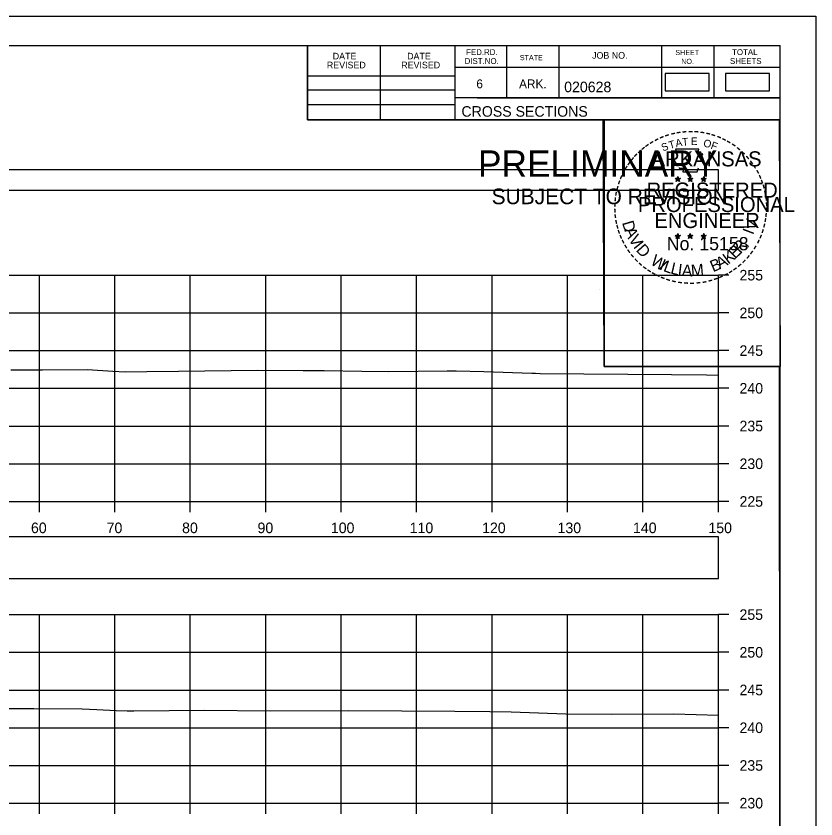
# Model space of a CAD drawing. Extents: x 1369627 to 1374022, y 380035 to 398173.
# Drawn here: x 1372155.4 to 1372261.5, y 382279 to 382385.5 of the extents above; entities that cross this region are included whole.
import ezdxf

# ---------------------------------------------------------------- set-up
doc = ezdxf.new("R2010")
doc.units = 0
for name, color, linetype in [('Default', 7, 'Continuous'), ('R_Axis', 7, 'Continuous'), ('R_Axis Annot', 7, 'Continuous'), ('R_Border', 7, 'Continuous'), ('R_Border PE', 7, 'Continuous'), ('R_Border Prem', 7, 'Continuous'), ('R_Exist Surface', 7, 'Continuous'), ('R_Grid', 7, 'Continuous'), ('R_No Plot', 7, 'Continuous')]:
    doc.layers.add(name, color=color, linetype=linetype)

msp = doc.modelspace()

# ---------------------------------------------------------------- linework, layer by layer
at = {"layer": 'Default'}
for points in [[(1372241.46, 382375.56), (1372247.3, 382375.56), (1372247.3, 382377.87), (1372241.46, 382377.87)], [(1372249.48, 382375.56), (1372255.32, 382375.56), (1372255.32, 382377.87), (1372249.48, 382377.87)], [(1371948.53, 382362.4), (1372248.53, 382362.4), (1372248.53, 382365.11), (1371948.53, 382365.11)], [(1371948.53, 382310.92), (1372248.53, 382310.92), (1372248.53, 382316.44), (1371948.53, 382316.44)]]:
    msp.add_lwpolyline(points, close=True, dxfattribs=at)
at = {"layer": 'R_Axis'}
for p, q in [((1372248.53, 382321.14), (1372248.53, 382351.14)), ((1372249.93, 382351.14), (1372248.53, 382351.14)), ((1372249.93, 382346.14), (1372248.53, 382346.14)), ((1372249.93, 382341.14), (1372248.53, 382341.14)), ((1372249.93, 382336.14), (1372248.53, 382336.14)), ((1372249.93, 382331.14), (1372248.53, 382331.14)), ((1372249.93, 382326.14), (1372248.53, 382326.14)), ((1371948.53, 382321.14), (1372248.53, 382321.14)), ((1372158.53, 382319.74), (1372158.53, 382321.14)), ((1372168.53, 382319.74), (1372168.53, 382321.14)), ((1372178.53, 382319.74), (1372178.53, 382321.14)), ((1372188.53, 382319.74), (1372188.53, 382321.14)), ((1372198.53, 382319.74), (1372198.53, 382321.14)), ((1372208.53, 382319.74), (1372208.53, 382321.14)), ((1372218.53, 382319.74), (1372218.53, 382321.14)), ((1372228.53, 382319.74), (1372228.53, 382321.14)), ((1372238.53, 382319.74), (1372238.53, 382321.14)), ((1372248.53, 382319.74), (1372248.53, 382321.14)), ((1372249.93, 382321.14), (1372248.53, 382321.14)), ((1372248.53, 382281.14), (1372248.53, 382306.14)), ((1372249.93, 382306.14), (1372248.53, 382306.14)), ((1372249.93, 382301.14), (1372248.53, 382301.14)), ((1372249.93, 382296.14), (1372248.53, 382296.14)), ((1372249.93, 382291.14), (1372248.53, 382291.14)), ((1372249.93, 382286.14), (1372248.53, 382286.14)), ((1371948.53, 382281.14), (1372248.53, 382281.14)), ((1372158.53, 382279.74), (1372158.53, 382281.14)), ((1372168.53, 382279.74), (1372168.53, 382281.14)), ((1372178.53, 382279.74), (1372178.53, 382281.14)), ((1372188.53, 382279.74), (1372188.53, 382281.14)), ((1372198.53, 382279.74), (1372198.53, 382281.14)), ((1372208.53, 382279.74), (1372208.53, 382281.14)), ((1372218.53, 382279.74), (1372218.53, 382281.14)), ((1372228.53, 382279.74), (1372228.53, 382281.14)), ((1372238.53, 382279.74), (1372238.53, 382281.14)), ((1372248.53, 382279.74), (1372248.53, 382281.14)), ((1372249.93, 382281.14), (1372248.53, 382281.14))]:
    msp.add_line(p, q, dxfattribs=at)
at = {"layer": 'R_Border'}
for p, q in [((1371940.53, 382381.6), (1372256.71, 382381.6)), ((1372194.07, 382371.72), (1372194.07, 382381.6)), ((1372203.75, 382371.72), (1372203.75, 382381.6)), ((1372213.61, 382381.6), (1372213.61, 382371.72)), ((1372220.45, 382381.6), (1372220.45, 382374.66)), ((1372227.39, 382381.6), (1372227.39, 382374.66)), ((1372240.97, 382381.6), (1372240.97, 382374.66)), ((1372247.91, 382381.6), (1372247.91, 382374.66)), ((1372256.71, 382176.14), (1372256.71, 382381.6)), ((1372256.71, 382378.66), (1372213.61, 382378.66)), ((1372256.71, 382378.68), (1372256.71, 382378.68)), ((1372194.07, 382377.58), (1372213.61, 382377.58)), ((1372194.07, 382375.72), (1372213.61, 382375.72)), ((1372256.71, 382374.66), (1372213.61, 382374.66)), ((1372216.57, 382374.66), (1372256.71, 382374.66)), ((1372194.07, 382373.78), (1372213.61, 382373.78)), ((1372256.71, 382371.72), (1372194.07, 382371.72))]:
    msp.add_line(p, q, dxfattribs=at)
at = {"layer": 'R_Border PE'}
for p, q in [((1372242.79, 382363.97), (1372243.14, 382363.86)), ((1372242.79, 382363.97), (1372243.05, 382363.93)), ((1372242.79, 382363.97), (1372243.03, 382363.85)), ((1372242.93, 382363.57), (1372243.14, 382363.86)), ((1372242.93, 382363.57), (1372243.05, 382363.81)), ((1372242.93, 382363.57), (1372243.14, 382363.78)), ((1372243.14, 382364.23), (1372243.1, 382363.98)), ((1372243.14, 382363.86), (1372243.14, 382364.23)), ((1372243.14, 382364.23), (1372243.19, 382363.98)), ((1372243.49, 382363.97), (1372243.14, 382363.86)), ((1372243.36, 382363.57), (1372243.14, 382363.86)), ((1372243.36, 382363.57), (1372243.14, 382363.78)), ((1372243.49, 382363.97), (1372243.2, 382363.93)), ((1372243.36, 382363.57), (1372243.22, 382363.86)), ((1372243.49, 382363.97), (1372243.29, 382363.87)), ((1372244.46, 382363.97), (1372244.81, 382363.86)), ((1372244.46, 382363.97), (1372244.72, 382363.93)), ((1372244.46, 382363.97), (1372244.7, 382363.85)), ((1372244.6, 382363.57), (1372244.81, 382363.86)), ((1372244.6, 382363.57), (1372244.72, 382363.81)), ((1372244.6, 382363.57), (1372244.81, 382363.78)), ((1372244.81, 382364.23), (1372244.77, 382363.98)), ((1372244.81, 382363.86), (1372244.81, 382364.23)), ((1372244.81, 382364.23), (1372244.86, 382363.98)), ((1372245.16, 382363.97), (1372244.81, 382363.86)), ((1372245.03, 382363.57), (1372244.81, 382363.86)), ((1372245.03, 382363.57), (1372244.81, 382363.78)), ((1372245.16, 382363.97), (1372244.87, 382363.93)), ((1372245.03, 382363.57), (1372244.89, 382363.86)), ((1372245.16, 382363.97), (1372244.96, 382363.87)), ((1372246.23, 382363.96), (1372246.58, 382363.85)), ((1372246.23, 382363.96), (1372246.48, 382363.92)), ((1372246.23, 382363.96), (1372246.47, 382363.84)), ((1372246.36, 382363.55), (1372246.58, 382363.85)), ((1372246.36, 382363.55), (1372246.49, 382363.8)), ((1372246.36, 382363.55), (1372246.58, 382363.77)), ((1372246.58, 382364.22), (1372246.54, 382363.96)), ((1372246.58, 382363.85), (1372246.58, 382364.22)), ((1372246.58, 382364.22), (1372246.63, 382363.97)), ((1372246.92, 382363.96), (1372246.58, 382363.85)), ((1372246.79, 382363.55), (1372246.58, 382363.85)), ((1372246.79, 382363.55), (1372246.58, 382363.77)), ((1372246.92, 382363.96), (1372246.64, 382363.91)), ((1372246.79, 382363.55), (1372246.65, 382363.85)), ((1372246.92, 382363.96), (1372246.72, 382363.86)), ((1372242.79, 382356.4), (1372243.14, 382356.29)), ((1372242.79, 382356.4), (1372243.04, 382356.36)), ((1372242.79, 382356.4), (1372243.03, 382356.28)), ((1372242.92, 382355.99), (1372243.14, 382356.29)), ((1372242.92, 382355.99), (1372243.05, 382356.24)), ((1372242.92, 382355.99), (1372243.14, 382356.21)), ((1372243.14, 382356.66), (1372243.1, 382356.4)), ((1372243.14, 382356.29), (1372243.14, 382356.66)), ((1372243.14, 382356.66), (1372243.19, 382356.41)), ((1372243.49, 382356.4), (1372243.14, 382356.29)), ((1372243.35, 382355.99), (1372243.14, 382356.29)), ((1372243.35, 382355.99), (1372243.14, 382356.21)), ((1372243.49, 382356.4), (1372243.2, 382356.35)), ((1372243.35, 382355.99), (1372243.22, 382356.28)), ((1372243.49, 382356.4), (1372243.28, 382356.3)), ((1372244.46, 382356.4), (1372244.81, 382356.29)), ((1372244.46, 382356.4), (1372244.71, 382356.36)), ((1372244.46, 382356.4), (1372244.7, 382356.28)), ((1372244.59, 382355.99), (1372244.81, 382356.29)), ((1372244.59, 382355.99), (1372244.72, 382356.24)), ((1372244.59, 382355.99), (1372244.81, 382356.21)), ((1372244.81, 382356.66), (1372244.77, 382356.4)), ((1372244.81, 382356.29), (1372244.81, 382356.66)), ((1372244.81, 382356.66), (1372244.86, 382356.41)), ((1372245.16, 382356.4), (1372244.81, 382356.29)), ((1372245.02, 382355.99), (1372244.81, 382356.29)), ((1372245.02, 382355.99), (1372244.81, 382356.21)), ((1372245.16, 382356.4), (1372244.87, 382356.35)), ((1372245.02, 382355.99), (1372244.88, 382356.28)), ((1372245.16, 382356.4), (1372244.95, 382356.3)), ((1372246.23, 382356.39), (1372246.58, 382356.28)), ((1372246.23, 382356.39), (1372246.48, 382356.35)), ((1372246.23, 382356.39), (1372246.46, 382356.27)), ((1372246.36, 382355.98), (1372246.58, 382356.28)), ((1372246.36, 382355.98), (1372246.49, 382356.23)), ((1372246.36, 382355.98), (1372246.57, 382356.2)), ((1372246.58, 382356.65), (1372246.53, 382356.39)), ((1372246.79, 382355.98), (1372246.57, 382356.2)), ((1372246.58, 382356.28), (1372246.58, 382356.65)), ((1372246.58, 382356.65), (1372246.62, 382356.4)), ((1372246.92, 382356.39), (1372246.58, 382356.28)), ((1372246.79, 382355.98), (1372246.58, 382356.28)), ((1372246.92, 382356.39), (1372246.64, 382356.34)), ((1372246.79, 382355.98), (1372246.65, 382356.27)), ((1372246.92, 382356.39), (1372246.72, 382356.29))]:
    msp.add_line(p, q, dxfattribs=at)
for points in [[(1372242.84, 382367.85), (1372243.1, 382367.03)], [(1372246.35, 382366.93), (1372246.49, 382367.21), (1372245.8, 382367.19), (1372245.95, 382367.85), (1372242.84, 382367.85)], [(1372243.33, 382365.43), (1372243.33, 382365.34), (1372243.89, 382365.32), (1372243.84, 382364.85), (1372245.71, 382364.85), (1372245.91, 382365.39)], [(1372243.14, 382364.23), (1372243.36, 382363.57), (1372242.79, 382363.97), (1372243.49, 382363.97), (1372242.93, 382363.57), (1372243.14, 382364.23)], [(1372244.81, 382364.23), (1372245.03, 382363.57), (1372244.46, 382363.97), (1372245.16, 382363.97), (1372244.6, 382363.57), (1372244.81, 382364.23)], [(1372246.58, 382364.22), (1372246.79, 382363.55), (1372246.23, 382363.96), (1372246.92, 382363.96), (1372246.36, 382363.55), (1372246.58, 382364.22)], [(1372243.14, 382356.66), (1372243.35, 382355.99), (1372242.79, 382356.4), (1372243.49, 382356.4), (1372242.92, 382355.99), (1372243.14, 382356.66)], [(1372244.81, 382356.66), (1372245.02, 382355.99), (1372244.46, 382356.4), (1372245.16, 382356.4), (1372244.59, 382355.99), (1372244.81, 382356.66)], [(1372246.58, 382356.65), (1372246.79, 382355.98), (1372246.23, 382356.39), (1372246.92, 382356.39), (1372246.36, 382355.98), (1372246.58, 382356.65)]]:
    msp.add_lwpolyline(points, dxfattribs=at)
for centre, radius in [((1372243.14, 382363.86), 0.172), ((1372243.14, 382363.86), 0.145), ((1372243.14, 382363.86), 0.116), ((1372243.14, 382363.86), 0.0991), ((1372243.14, 382363.86), 0.0747), ((1372243.14, 382363.86), 0.0495), ((1372243.14, 382363.86), 0.0296), ((1372244.81, 382363.86), 0.172), ((1372244.81, 382363.86), 0.145), ((1372244.81, 382363.86), 0.116), ((1372244.81, 382363.86), 0.0991), ((1372244.81, 382363.86), 0.0747), ((1372244.81, 382363.86), 0.0495), ((1372244.81, 382363.86), 0.0296), ((1372246.58, 382363.85), 0.172), ((1372246.58, 382363.85), 0.145), ((1372246.58, 382363.85), 0.116), ((1372246.58, 382363.85), 0.0991), ((1372246.58, 382363.85), 0.0747), ((1372246.58, 382363.85), 0.0495), ((1372246.58, 382363.85), 0.0296), ((1372243.14, 382356.29), 0.172), ((1372243.14, 382356.29), 0.145), ((1372243.14, 382356.29), 0.116), ((1372243.14, 382356.29), 0.0991), ((1372243.14, 382356.29), 0.0747), ((1372243.14, 382356.29), 0.0495), ((1372243.14, 382356.29), 0.0296), ((1372244.81, 382356.29), 0.172), ((1372244.81, 382356.29), 0.145), ((1372244.81, 382356.29), 0.116), ((1372244.81, 382356.29), 0.0991), ((1372244.81, 382356.29), 0.0747), ((1372244.81, 382356.29), 0.0495), ((1372244.81, 382356.29), 0.0296), ((1372246.57, 382356.28), 0.172), ((1372246.57, 382356.28), 0.145), ((1372246.57, 382356.28), 0.116), ((1372246.57, 382356.28), 0.0991), ((1372246.57, 382356.28), 0.0747), ((1372246.57, 382356.28), 0.0495), ((1372246.57, 382356.28), 0.0296)]:
    msp.add_circle(centre, radius, dxfattribs=at)
at = {"layer": 'R_Exist Surface'}
for points in [[(1372154.72, 382338.6), (1372158.92, 382338.6), (1372164.88, 382338.64), (1372168.24, 382338.41), (1372169.89, 382338.33), (1372172.75, 382338.36), (1372176.97, 382338.43), (1372187.45, 382338.54), (1372193.51, 382338.51), (1372196.29, 382338.49), (1372201.27, 382338.43), (1372204.85, 382338.35), (1372212.56, 382338.48), (1372213.76, 382338.47), (1372217.45, 382338.39), (1372223.79, 382338.13), (1372224.3, 382338.13), (1372224.9, 382338.12), (1372242.3, 382337.96), (1372246.94, 382337.91), (1372248.53, 382337.89)], [(1372153.04, 382293.71), (1372157.77, 382293.68), (1372164.2, 382293.66), (1372166.12, 382293.54), (1372168.72, 382293.44), (1372170.18, 382293.38), (1372171.06, 382293.39), (1372180.43, 382293.46), (1372189.13, 382293.4), (1372199.53, 382293.43), (1372213.61, 382293.35), (1372218.23, 382293.28), (1372221.07, 382293.26), (1372228.29, 382292.99), (1372234.31, 382292.95), (1372242.64, 382292.97), (1372248.53, 382292.81)]]:
    msp.add_lwpolyline(points, dxfattribs=at)
at = {"layer": 'R_Grid'}
for p, q in [((1371948.53, 382351.14), (1372248.53, 382351.14)), ((1372158.53, 382321.14), (1372158.53, 382351.14)), ((1372168.53, 382321.14), (1372168.53, 382351.14)), ((1372178.53, 382321.14), (1372178.53, 382351.14)), ((1372188.53, 382321.14), (1372188.53, 382351.14)), ((1372198.53, 382321.14), (1372198.53, 382351.14)), ((1372208.53, 382321.14), (1372208.53, 382351.14)), ((1372218.53, 382321.14), (1372218.53, 382351.14)), ((1372228.53, 382321.14), (1372228.53, 382351.14)), ((1372238.53, 382321.14), (1372238.53, 382351.14)), ((1372248.53, 382321.14), (1372248.53, 382351.14)), ((1371948.53, 382346.14), (1372248.53, 382346.14)), ((1371948.53, 382341.14), (1372248.53, 382341.14)), ((1371948.53, 382336.14), (1372248.53, 382336.14)), ((1371948.53, 382331.14), (1372248.53, 382331.14)), ((1371948.53, 382326.14), (1372248.53, 382326.14)), ((1371948.53, 382321.14), (1372248.53, 382321.14)), ((1371948.53, 382306.14), (1372248.53, 382306.14)), ((1372158.53, 382281.14), (1372158.53, 382306.14)), ((1372168.53, 382281.14), (1372168.53, 382306.14)), ((1372178.53, 382281.14), (1372178.53, 382306.14)), ((1372188.53, 382281.14), (1372188.53, 382306.14)), ((1372198.53, 382281.14), (1372198.53, 382306.14)), ((1372208.53, 382281.14), (1372208.53, 382306.14)), ((1372218.53, 382281.14), (1372218.53, 382306.14)), ((1372228.53, 382281.14), (1372228.53, 382306.14)), ((1372238.53, 382281.14), (1372238.53, 382306.14)), ((1372248.53, 382281.14), (1372248.53, 382306.14)), ((1371948.53, 382301.14), (1372248.53, 382301.14)), ((1371948.53, 382296.14), (1372248.53, 382296.14)), ((1371948.53, 382291.14), (1372248.53, 382291.14)), ((1371948.53, 382286.14), (1372248.53, 382286.14)), ((1371948.53, 382281.14), (1372248.53, 382281.14))]:
    msp.add_line(p, q, dxfattribs=at)
at = {"layer": 'R_No Plot'}
for p, q in [((1371928.13, 382385.49), (1372261.46, 382385.49)), ((1372232.74, 382349.26), (1372232.74, 382349.26))]:
    msp.add_line(p, q, dxfattribs=at)
for points in [[(1371928.12, 382385.49), (1372261.46, 382385.49), (1372261.46, 382172.16), (1371928.12, 382172.16)], [(1372174.45, 382381.6), (1372194.07, 382381.6), (1372194.07, 382371.72), (1372210.18, 382371.72), (1372233.38, 382371.72), (1372233.38, 382339.05), (1372256.59, 382339.05), (1372256.71, 382176.14), (1371940.53, 382176.14), (1371940.53, 382381.6)], [(1372233.24, 382371.72), (1372256.59, 382371.72), (1372256.73, 382339.05), (1372233.38, 382339.05)]]:
    msp.add_lwpolyline(points, close=True, dxfattribs=at)

# ---------------------------------------------------------------- texts
at = {"layer": 'R_Axis Annot'}
for s, p in [('255', (1372251.33, 382350.44)), ('250', (1372251.33, 382345.44)), ('245', (1372251.33, 382340.44)), ('240', (1372251.33, 382335.44)), ('235', (1372251.33, 382330.44)), ('230', (1372251.33, 382325.44)), ('225', (1372251.33, 382320.44)), ('60', (1372157.41, 382316.94)), ('70', (1372167.44, 382316.94)), ('80', (1372177.44, 382316.94)), ('90', (1372187.44, 382316.94)), ('100', (1372197.16, 382316.94)), ('110', (1372207.61, 382316.94)), ('120', (1372217.21, 382316.94)), ('130', (1372227.21, 382316.94)), ('140', (1372237.21, 382316.94)), ('150', (1372247.21, 382316.94)), ('255', (1372251.33, 382305.44)), ('250', (1372251.33, 382300.44)), ('245', (1372251.33, 382295.44)), ('240', (1372251.33, 382290.44)), ('235', (1372251.33, 382285.44)), ('230', (1372251.33, 382280.44))]:
    msp.add_text(s, height=1.4, dxfattribs=at).set_placement(p)
at = {"layer": 'R_Border'}
for s, height, p in [('FED.RD.', 0.782, (1372215.09, 382380.32)), ('JOB NO.', 0.879, (1372231.79, 382379.84)), ('SHEET', 0.684, (1372242.83, 382380.32)), ('TOTAL', 0.782, (1372250.35, 382380.32)), ('DATE', 0.879, (1372197.41, 382379.74)), ('DATE', 0.879, (1372207.27, 382379.74)), ('DIST.NO.', 0.782, (1372214.89, 382379.14)), ('STATE', 0.684, (1372222.21, 382379.64)), ('NO.', 0.684, (1372243.61, 382379.14)), ('SHEETS', 0.782, (1372250.07, 382379.14)), ('REVISED', 0.879, (1372196.63, 382378.56)), ('REVISED', 0.879, (1372206.49, 382378.56)), ('6', 1.17, (1372216.45, 382375.92)), ('ARK.', 1.172, (1372222.11, 382375.92)), ('020628', 1.4, (1372228.09, 382375.4)), ('CROSS SECTIONS', 1.4, (1372214.47, 382372.15))]:
    msp.add_text(s, height=height, rotation=360, dxfattribs=at).set_placement(p)
at = {"layer": 'R_Border PE'}
for s, height, rotation, p in [('-', 1.6, 13.6301, (1372242.33, 382369.22)), ('-', 1.6, 10.2193, (1372243.01, 382369.38)), ('-', 1.6, 5.8968, (1372243.74, 382369.49)), ('-', 1.6, 0.1862, (1372244.51, 382369.56)), ('-', 1.6, 357.743, (1372245.24, 382369.55)), ('-', 1.6, 352.1617, (1372245.98, 382369.5)), ('-', 1.6, 347.2049, (1372246.7, 382369.38)), ('-', 1.6, 34.0636, (1372239.72, 382368.02)), ('-', 1.6, 28.7918, (1372240.32, 382368.39)), ('-', 1.6, 24.3072, (1372240.95, 382368.71)), ('-', 1.6, 19.1761, (1372241.58, 382368.98)), ('T', 1, 16.4036, (1372242.1, 382367.86)), ('A', 1, 11.2132, (1372242.93, 382368.11)), ('T', 1, 6.0228, (1372243.78, 382368.28)), ('E', 1, 0.8323, (1372244.88, 382368.39)), ('O', 1, 350.4515, (1372246.49, 382368.18)), ('-', 1.6, 342.3362, (1372247.33, 382369.23)), ('-', 1.6, 337.8551, (1372248.07, 382369)), ('-', 1.6, 334.1211, (1372248.7, 382368.73)), ('-', 1.6, 329.6409, (1372249.28, 382368.45)), ('-', 1.6, 38.9507, (1372238.67, 382367.25)), ('-', 1.6, 36.2317, (1372239.14, 382367.63)), ('S', 1, 21.594, (1372241.19, 382367.53)), ('F', 1, 340.0707, (1372247.44, 382367.95)), ('-', 1.6, 325.8627, (1372249.92, 382368.09)), ('-', 1.6, 320.5297, (1372250.53, 382367.66)), ('-', 1.6, 48.423, (1372237.78, 382366.36)), ('-', 1.6, 42.9622, (1372238.23, 382366.83)), ('ARKANSAS', 2, 360, (1372239.69, 382365.56)), ('-', 1.6, 315.5786, (1372251.13, 382367.17)), ('-', 1.6, 309.8797, (1372251.7, 382366.62)), ('-', 1.6, 54.2325, (1372236.97, 382365.3)), ('-', 1.6, 50.6142, (1372237.38, 382365.87)), ('-', 1.6, 306.6522, (1372252.22, 382366.02)), ('-', 1.6, 62.8713, (1372236.33, 382364.16)), ('-', 1.6, 58.0706, (1372236.64, 382364.78)), ('-', 1.4, 303.6753, (1372252.71, 382365.45)), ('-', 1.6, 299.6684, (1372253.03, 382364.85)), ('-', 1.6, 72.3945, (1372235.85, 382362.92)), ('-', 1.6, 67.7743, (1372236.07, 382363.55)), ('-', 1.6, 294.6628, (1372253.35, 382364.24)), ('-', 1.6, 290.5728, (1372253.61, 382363.66)), ('-', 1.6, 75.461, (1372235.66, 382362.21)), ('REGISTERED', 2, 360, (1372239.01, 382361.42)), ('-', 1.6, 285.1233, (1372253.84, 382363.08)), ('-', 1.6, 81.2013, (1372235.52, 382361.49)), ('PROFESSIONAL', 2, 360, (1372237.86, 382359.51)), ('-', 1.6, 280.5493, (1372254.04, 382362.34)), ('-', 1.6, 276.5962, (1372254.21, 382361.57)), ('-', 1.6, 89.0622, (1372235.42, 382360.1)), ('-', 1.6, 85.1863, (1372235.45, 382360.8)), ('-', 1.6, 274.3301, (1372254.27, 382360.85)), ('-', 1.6, 94.1959, (1372235.46, 382359.38)), ('ENGINEER', 2, 360, (1372240.05, 382357.39)), ('-', 1.6, 263.5172, (1372254.28, 382359.55)), ('-', 1.6, 269.9407, (1372254.3, 382360.21)), ('-', 1.6, 98.9479, (1372235.53, 382358.71)), ('-', 1.6, 101.7149, (1372235.66, 382357.98)), ('D', 1.54, 286.2848, (1372235.75, 382358.11)), ('V', 1.54, 72.6573, (1372253.35, 382356.95)), ('-', 1.6, 260.9953, (1372254.21, 382358.89)), ('-', 1.6, 105.4578, (1372235.83, 382357.38)), ('I', 1.54, 69.0301, (1372253.12, 382356.41)), ('-', 1.6, 252.8681, (1372253.92, 382357.5)), ('-', 1.6, 255.7626, (1372254.1, 382358.22)), ('-', 1.6, 109.0874, (1372236.04, 382356.75)), ('-', 1.6, 114.0643, (1372236.3, 382356.15)), ('A', 1.54, 292.7835, (1372236.05, 382357.11)), ('V', 1.54, 300.7936, (1372236.56, 382355.93)), ('No. 15158', 1.757, 360, (1372241.69, 382354.44)), ('-', 1.6, 247.8887, (1372253.7, 382356.82)), ('-', 1.6, 115.7289, (1372236.6, 382355.54)), ('-', 1.6, 120.4471, (1372236.96, 382354.95)), ('I', 1.54, 308.3502, (1372237.19, 382354.9)), ('D', 1.54, 311.9774, (1372237.54, 382354.43)), ('E', 1.54, 44.0175, (1372250.74, 382353.22)), ('R', 1.54, 50.3651, (1372251.47, 382353.93)), (',', 1.54, 57.4684, (1372252.2, 382354.81)), ('-', 1.6, 244.6197, (1372253.43, 382356.19)), ('-', 1.6, 125.8934, (1372237.36, 382354.39)), ('K', 1.54, 36.9143, (1372249.83, 382352.53)), ('-', 1.6, 233.8452, (1372252.64, 382354.79)), ('-', 1.6, 239.0712, (1372253.04, 382355.44)), ('-', 1.6, 130.7181, (1372237.82, 382353.84)), ('-', 1.6, 134.2238, (1372238.34, 382353.29)), ('W', 1.54, 328.0731, (1372239.42, 382352.66)), ('I', 1.54, 336.6877, (1372240.61, 382351.95)), ('L', 1.54, 340.3149, (1372241.14, 382351.71)), ('B', 1.54, 22.8589, (1372247.82, 382351.52)), ('A', 1.54, 28.9042, (1372248.71, 382351.89)), ('-', 1.6, 225.7653, (1372251.73, 382353.66)), ('-', 1.6, 231.2538, (1372252.21, 382354.22)), ('-', 1.6, 138.9338, (1372238.86, 382352.83)), ('-', 1.6, 144.6463, (1372239.42, 382352.42)), ('-', 1.6, 148.0898, (1372239.98, 382352.05)), ('L', 1.54, 346.6625, (1372242.1, 382351.37)), ('I', 1.54, 353.0101, (1372243.09, 382351.13)), ('A', 1.54, 356.6373, (1372243.66, 382351.04)), ('M', 1.54, 4.6473, (1372244.95, 382350.99)), ('-', 1.6, 215.7363, (1372250.66, 382352.68)), ('-', 1.6, 221.0851, (1372251.21, 382353.15)), ('-', 1.6, 151.5704, (1372240.56, 382351.73)), ('-', 1.6, 154.6002, (1372241.08, 382351.48)), ('-', 1.6, 158.5612, (1372241.71, 382351.23)), ('AAMU', 0.00002, 360, (1372244.74, 382350.98)), ('-', 1.6, 204.2516, (1372248.94, 382351.63)), ('-', 1.6, 207.3568, (1372249.57, 382351.95)), ('-', 1.6, 212.2491, (1372250.12, 382352.29)), ('-', 1.6, 162.7983, (1372242.39, 382351.01)), ('-', 1.6, 167.5555, (1372243.11, 382350.85)), ('-', 1.6, 173.1155, (1372243.88, 382350.74)), ('-', 1.6, 176.5183, (1372244.63, 382350.69)), ('-', 1.6, 181.5918, (1372245.37, 382350.7)), ('-', 1.6, 185.8167, (1372246.18, 382350.78)), ('-', 1.6, 191.2858, (1372246.92, 382350.91)), ('-', 1.6, 195.4743, (1372247.65, 382351.11)), ('-', 1.6, 199.4643, (1372248.31, 382351.35))]:
    msp.add_text(s, height=height, rotation=rotation, dxfattribs=at).set_placement(p)
at = {"layer": 'R_Border Prem'}
for s, height, p in [('PRELIMINARY', 3.5, (1372216.66, 382364.18)), ('DWB', 0.01, (1372217.41, 382366.03)), ('SUBJECT TO REVISION', 2.0751, (1372218.47, 382360.55))]:
    msp.add_text(s, height=height, rotation=360, dxfattribs=at).set_placement(p)

doc.saveas('drawing.dxf')
